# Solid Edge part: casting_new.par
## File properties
Author: CADSoft
Template: Sync Iso Part.par
Last saved by: Cadcim
Revision: 15
Application: Solid Edge
Accuracy: 0.990
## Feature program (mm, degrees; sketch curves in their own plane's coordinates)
sketch for "unnamed Hole 1" plane through (40.5572, 0.1779, 68) normal (0, 0, 1) x-axis (1, 0, 0)
  hole centre (-1.5572, -0.1779) bore radius 6
hole "unnamed Hole 1" through
sketch for "unnamed Hole 2" plane through (-40.5572, 0.1779, 68) normal (0, 0, 1) x-axis (-1, 0, 0)
  hole centre (-1.5572, -0.1779) bore radius 6
hole "unnamed Hole 2" through
pattern "unnamed Pattern 1" of "unnamed Hole 1", "unnamed Hole 2"
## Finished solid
Body 1: solid body, 47 faces, 120 edges, 76 vertices.
  Faces by surface: plane 35, cylinder 10, torus 2
  Edges by curve: line 94, circle 21, intersection 5
Bounding box of the edges (mm; curved faces can reach further): 200.000 x 56.000 x 68.000, from (-100, -28, 0) to (100, 28, 68).
Cylindrical faces by radius (mm): R3 x1, R5 x4, R6 x2, R24 x1, R54 x2
Toroidal faces (ring radius, tube radius in mm): R62 r8 x2
Planar faces by outward normal: +x 6, +y 6, +z 7, -x 6, -y 6, -z 4
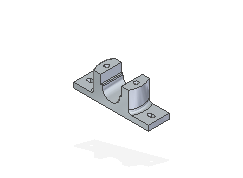
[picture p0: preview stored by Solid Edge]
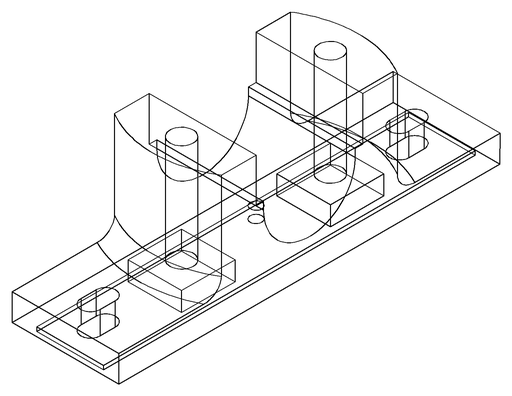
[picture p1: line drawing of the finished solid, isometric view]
